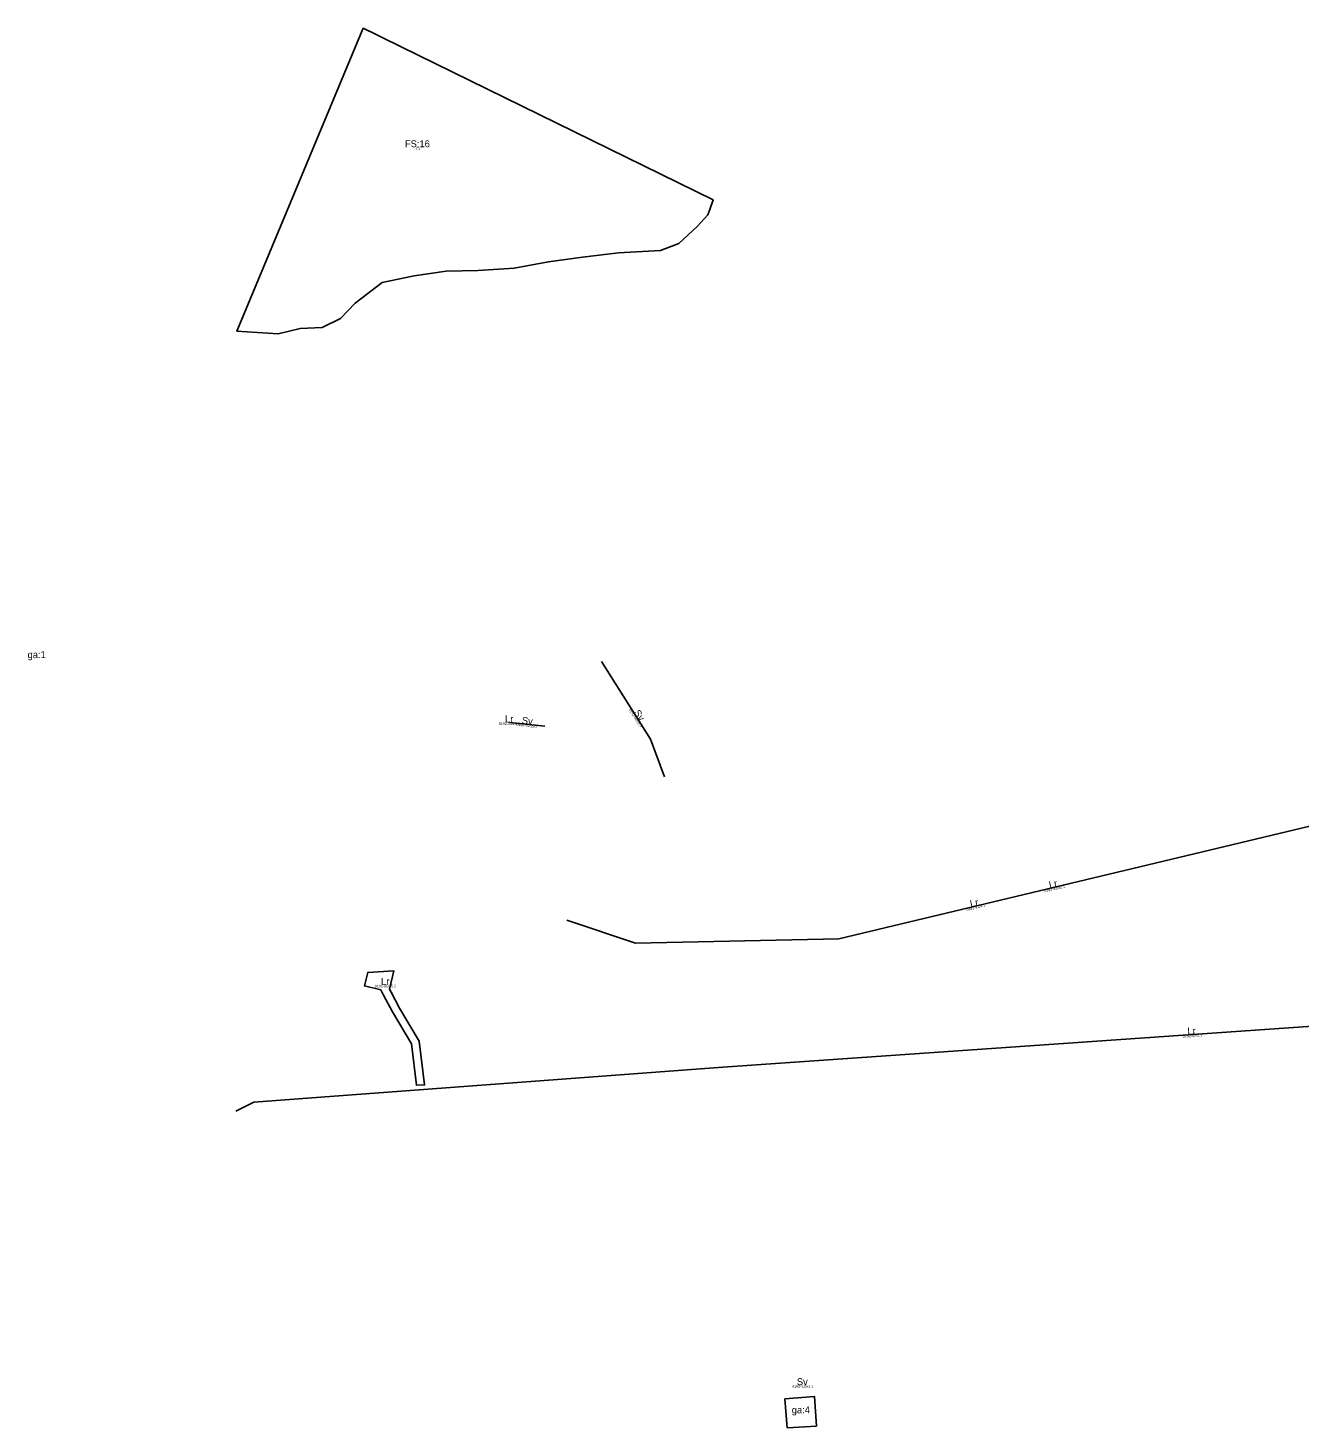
# Model space of a CAD drawing. Extents: x 140791 to 143631, y 6542790 to 6549933.
# Drawn here: x 141483 to 142121, y 6548066 to 6548769 of the extents above; entities that cross this region are included whole.
import ezdxf

# ---------------------------------------------------------------- set-up
doc = ezdxf.new("R2010")
doc.units = 0
for name, color, linetype in [('RATT Aktbeteckning för ledningsrätt', 7, 'Continuous'), ('RATT Aktbeteckning för servitut', 7, 'Continuous'), ('RATT Beteckning för fiske', 7, 'Continuous'), ('RATT Beteckning för gemensammhetsanläggning', 7, 'Continuous'), ('RATT Beteckning för ledningsrätt', 7, 'Continuous'), ('RATT Beteckning för servitut', 7, 'Continuous'), ('RATT Fiskegräns', 7, 'Continuous'), ('RATT Gemensamhetsanläggningsgräns', 7, 'Continuous'), ('RATT Ledningsrätt', 7, 'Continuous'), ('RATT Ledningsrättsgräns', 7, 'Continuous'), ('RATT Områdesnummer för fiske', 7, 'Continuous'), ('RATT Servitut', 7, 'Continuous')]:
    doc.layers.add(name, color=color, linetype=linetype)

msp = doc.modelspace()

# ---------------------------------------------------------------- linework, layer by layer
at = {"layer": 'RATT Fiskegräns'}
msp.add_lwpolyline([(141651.15, 6548768.54), (141657.63, 6548765.36), (141661.01, 6548763.69), (141826.77, 6548682.21), (141825.11, 6548677.44), (141824.21, 6548674.79), (141818.96, 6548669.01), (141809.57, 6548660.42), (141800.41, 6548656.81), (141779.34, 6548655.72), (141761.23, 6548653.5), (141744.12, 6548651.24), (141726.97, 6548647.99), (141708.9, 6548646.77), (141692.87, 6548646.46), (141676.76, 6548644.15), (141660.6, 6548640.85), (141647.14, 6548630.43), (141639.8, 6548622.75), (141630.59, 6548618.15), (141619.56, 6548617.62), (141608.44, 6548615.1), (141587.74, 6548616.33), (141651.15, 6548768.54)], dxfattribs=at)
at = {"layer": 'RATT Gemensamhetsanläggningsgräns'}
msp.add_lwpolyline([(141862.77, 6548080.36), (141864.07, 6548065.78), (141878.64, 6548066.72), (141877.71, 6548081.65), (141862.77, 6548080.36)], dxfattribs=at)
at = {"layer": 'RATT Ledningsrätt'}
for points in [[(141587.21, 6548224.88), (141596.19, 6548229.34), (141831.7, 6548246.84), (142154.26, 6548269.4), (142201.62, 6548465.33), (142204.3, 6548482.98)], [(141753.31, 6548320.76), (141787.82, 6548309.21), (141889.95, 6548311.37), (142153.72, 6548374.34), (142174.54, 6548380.37), (142230.06, 6548341.39)], [(141753.31, 6548320.76), (141787.82, 6548309.21), (141889.95, 6548311.37), (142153.72, 6548374.34), (142161.44, 6548376.57)]]:
    msp.add_lwpolyline(points, dxfattribs=at)
at = {"layer": 'RATT Ledningsrättsgräns'}
msp.add_lwpolyline([(141665.14, 6548284.5), (141669.41, 6548276.6), (141679.29, 6548259.94), (141681.93, 6548238.02), (141677.9, 6548237.83), (141675.42, 6548258.62), (141665.93, 6548274.63), (141661.4, 6548283.01), (141659.93, 6548285.73), (141651.78, 6548287.73), (141653.44, 6548294.5), (141666.61, 6548295.19), (141664.34, 6548285.98), (141665.14, 6548284.5)], dxfattribs=at)
at = {"layer": 'RATT Servitut'}
msp.add_line((141742.36, 6548418.12), (141724.56, 6548419.95), dxfattribs=at)
msp.add_lwpolyline([(141802.44, 6548392.7), (141795.33, 6548411.52), (141770.71, 6548450.55)], dxfattribs=at)

# ---------------------------------------------------------------- texts
at = {"layer": 'RATT Aktbeteckning för ledningsrätt'}
for s, p in [('0192-91/29.3', (141719.25, 6548418.65)), ('0192-05/45.2', (141657.03, 6548286.94))]:
    msp.add_text(s, height=1.3, dxfattribs=at).set_placement(p)
for s, rotation, p in [('0192-92/42.1', 13.178, (141993.24, 6548334.72)), ('0192-91/9.1', 13.178, (141954.11, 6548325.37)), ('0192-02/2.1', 4.193, (142062.7, 6548261.68))]:
    msp.add_text(s, height=1.3, rotation=rotation, dxfattribs=at).set_placement(p)
at = {"layer": 'RATT Aktbeteckning för servitut'}
for s, rotation, p in [('0192-91/29.4', 302.522, (141784.44, 6548426.3)), ('0192-91/29.2', 353.88, (141728.05, 6548418.31))]:
    msp.add_text(s, height=1.3, rotation=rotation, dxfattribs=at).set_placement(p)
msp.add_text('0192-92/63.1', height=1.3, dxfattribs=at).set_placement((141866.5, 6548085.97))
at = {"layer": 'RATT Beteckning för fiske'}
msp.add_text('FS:16', height=3.5, dxfattribs=at).set_placement((141672.12, 6548708.68))
at = {"layer": 'RATT Beteckning för gemensammhetsanläggning'}
for s, p in [('ga:1', (141482.68, 6548452.23)), ('ga:4', (141866.29, 6548073.11))]:
    msp.add_text(s, height=3.5, dxfattribs=at).set_placement(p)
at = {"layer": 'RATT Beteckning för ledningsrätt'}
for p in [(141722.35, 6548419.95), (141660.12, 6548288.24)]:
    msp.add_text('Lr', height=3.5, dxfattribs=at).set_placement(p)
for rotation, p in [(13.178, (141995.84, 6548336.66)), (13.178, (141956.22, 6548327.2)), (4.193, (142065.07, 6548263.15))]:
    msp.add_text('Lr', height=3.5, rotation=rotation, dxfattribs=at).set_placement(p)
at = {"layer": 'RATT Beteckning för servitut'}
for rotation, p in [(302.522, (141786.87, 6548424.91)), (353.88, (141730.65, 6548419.34))]:
    msp.add_text('Sv', height=3.5, rotation=rotation, dxfattribs=at).set_placement(p)
msp.add_text('Sv', height=3.5, dxfattribs=at).set_placement((141868.86, 6548087.27))
at = {"layer": 'RATT Områdesnummer för fiske'}
msp.add_text('F1', height=1.3, dxfattribs=at).set_placement((141677.63, 6548707.38))

doc.saveas('drawing.dxf')
